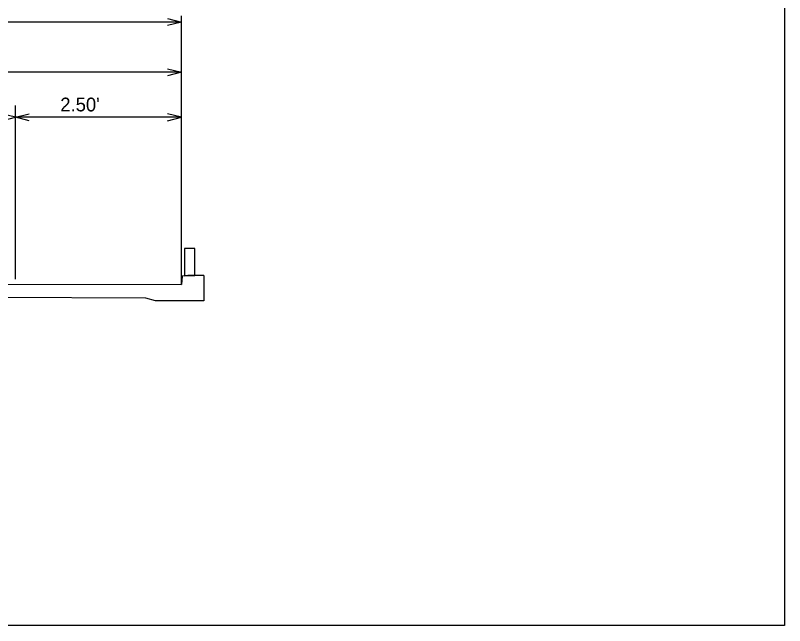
# Model space of a CAD drawing. Extents: x 8771 to 81668, y 6145 to 11018.
# Drawn here: x 15600 to 16868, y 7924 to 8930 of the extents above; entities that cross this region are included whole.
import ezdxf

# ---------------------------------------------------------------- set-up
doc = ezdxf.new("R2010")
doc.units = 0
for name, color, linetype in [('dsnCellElements', 7, 'Continuous'), ('DsnShtRevisedText', 7, 'Continuous'), ('SheetBorder', 7, 'Continuous'), ('ShtPlotIdentification', 7, 'Continuous')]:
    doc.layers.add(name, color=color, linetype=linetype)

msp = doc.modelspace()

# ---------------------------------------------------------------- linework, layer by layer
at = {"layer": 'dsnCellElements'}
for p, q in [((15873.4, 8486.3), (15873.4, 8929.1)), ((15873.4, 8919), (14624.8, 8919)), ((15873.4, 8836.3), (15249.1, 8836.3)), ((15599.8, 8495.4), (15599.8, 8781.6)), ((15599.8, 8495.4), (15599.8, 8781.6)), ((15599.8, 8495.4), (15599.8, 8781.6)), ((15599.8, 8495.4), (15599.8, 8781.6)), ((15873.4, 8762.1), (15599.8, 8762.1)), ((15878.6, 8500.6), (15883.8, 8501.1)), ((15883.8, 8501.1), (15895.3, 8501.1)), ((15814.6, 8463.9), (15249.1, 8466.8)), ((15830.8, 8459.5), (15814.6, 8463.9))]:
    msp.add_line(p, q, dxfattribs=at)
for points in [[(15850.7, 8924.7), (15873.4, 8919), (15850.7, 8913.3)], [(15850.7, 8842), (15873.4, 8836.3), (15850.7, 8830.6)], [(15577.1, 8756.4), (15599.8, 8762.1), (15577.1, 8767.8)], [(15622.5, 8756.4), (15599.8, 8762.1), (15622.5, 8767.8)], [(15850.7, 8756.4), (15873.4, 8762.1), (15850.7, 8767.8)], [(15895.3, 8501.1), (15895.3, 8545.6), (15878.6, 8545.6), (15878.6, 8500.6)], [(15910.3, 8501.1), (15910.3, 8459.5), (15830.8, 8459.5)], [(15910.3, 8501.1), (15883.8, 8501.1), (15874.8, 8500.2), (15873.4, 8486.3)]]:
    msp.add_lwpolyline(points, dxfattribs=at)
at = {"layer": 'DsnShtRevisedText'}
msp.add_lwpolyline([(15895.3, 8501.1), (15895.3, 8545.6), (15878.6, 8545.6), (15878.6, 8500.6)], dxfattribs=at)
at = {"layer": 'SheetBorder'}
msp.add_lwpolyline([(13732.5, 9944), (16867.5, 9944), (16867.5, 7924), (13732.5, 7924)], close=True, dxfattribs=at)
at = {"layer": 'ShtPlotIdentification'}
msp.add_line((15249.1, 8487.9), (15873.4, 8486.3), dxfattribs=at)

# ---------------------------------------------------------------- texts
at = {"layer": 'dsnCellElements'}
msp.add_text("2.50'", height=22.71, dxfattribs=at).set_placement((15673.8, 8771.7))

doc.saveas('drawing.dxf')
